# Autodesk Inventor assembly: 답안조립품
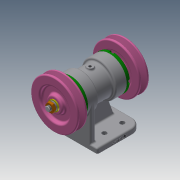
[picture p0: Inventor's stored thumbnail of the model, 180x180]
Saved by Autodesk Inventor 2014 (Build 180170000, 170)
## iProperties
Created: 2020-06
Part Number: 답안조립품
Document SubType Name: Assembly
Designer: kh
Author: kh
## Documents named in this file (13)
- C:\Users\kh\Desktop\700606V1032\답안조립품.iam
- C:\Users\kh\Desktop\700606V1032\본체.ipt
- C:\Users\kh\Desktop\700606V1032\축.ipt
- C:\Users\kh\Desktop\700606V1032\Ű 5x5x12.ipt
- C:\Users\kh\Desktop\700606V1032\커버.ipt
- C:\Users\kh\Desktop\700606V1032\볼트 M4.ipt
- C:\Users\kh\Desktop\700606V1032\오일 실 20 32 5.ipt
- C:\Users\kh\Desktop\700606V1032\베어링 6204.ipt
- C:\Users\kh\Desktop\700606V1032\커버_MIR.ipt
- C:\Users\kh\Desktop\700606V1032\V-벨트풀리.ipt
- C:\Users\kh\Desktop\700606V1032\너트 M10.ipt
- C:\Users\kh\Desktop\700606V1032\스프링 와셔 10.ipt
- C:\Users\kh\Desktop\700606V1032\평면 와셔 10x21.ipt
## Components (4 placed, 2 different names)
1. Ű 5x5x12:1 — Mate:1, Mate:5, Mate:6, Mate:37
2. Ű 5x5x12:2 — Mate:2, Mate:3, Mate:4, Mate:22
3. V-벨트풀리:1 — Mate:21, Mate:22, Mate:28, Mate:29
4. V-벨트풀리:2 — Mate:33, Mate:37, Mate:38
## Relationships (13: Mate 13)
- Mate:1: Ű 5x5x12:1
- Mate:2: Ű 5x5x12:2
- Mate:3: Ű 5x5x12:2
- Mate:4: Ű 5x5x12:2
- Mate:5: Ű 5x5x12:1
- Mate:6: Ű 5x5x12:1
- Mate:21: V-벨트풀리:1
- Mate:22: Ű 5x5x12:2 ↔ V-벨트풀리:1
- Mate:28: V-벨트풀리:1
- Mate:29: V-벨트풀리:1
- Mate:33: V-벨트풀리:2
- Mate:37: Ű 5x5x12:1 ↔ V-벨트풀리:2
- Mate:38: V-벨트풀리:2
## Named parameters: d35_d33 = 0, d36_d31 = 0, d37_d32 = 0
